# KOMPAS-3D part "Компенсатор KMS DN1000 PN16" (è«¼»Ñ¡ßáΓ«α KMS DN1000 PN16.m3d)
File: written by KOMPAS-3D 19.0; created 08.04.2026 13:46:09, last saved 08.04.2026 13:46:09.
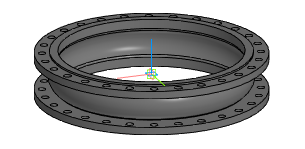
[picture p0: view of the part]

Document properties: Автор: Энергия; Полное имя файла: Z:\3.Личные\kachalov\3d для проектировщиков\7.1 Компенсатор\stp_Компенсатор KSM\Компенсатор KMS DN1000 PN16.m3d

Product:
- Part/product: Компенсатор KMS DN1000 PN16

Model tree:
1. Операция без истории:1  (labels: Компенсатор KMS DN1000 PN16)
